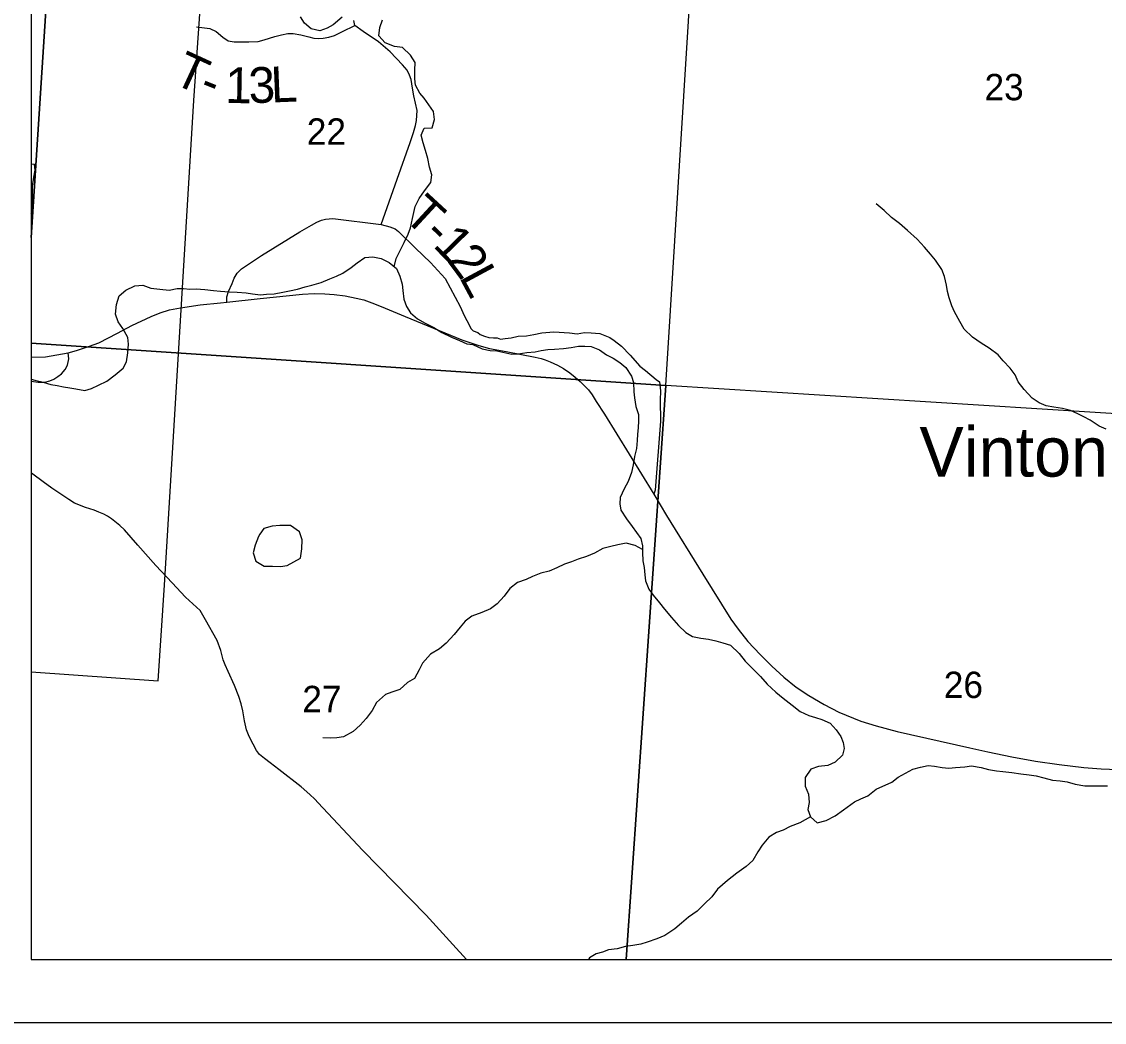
# Model space of a CAD drawing. Extents: x 0 to 34, y 0 to 22.
# Drawn here: x 2.085 to 3.804, y 14 to 15.589 of the extents above; entities that cross this region are included whole.
import ezdxf

# ---------------------------------------------------------------- set-up
doc = ezdxf.new("R2010")
doc.units = 0
for name, color, linetype in [('Default', 7, 'Continuous'), ('GM_X_City_Street', 7, 'Continuous'), ('GM_X_Minor_Lake', 7, 'Continuous'), ('GM_X_Minor_River', 7, 'Continuous'), ('GM_X_Section', 7, 'Continuous'), ('GM_X_Section_Text', 7, 'Continuous'), ('GM_X_Township_Road', 7, 'Continuous'), ('GM_X_Township_Road_Text', 7, 'Continuous'), ('GM_X_Unincorporated_Text', 7, 'Continuous'), ('GM_X_US_Route', 7, 'Continuous'), ('SC_Scratch1', 7, 'Continuous'), ('SH_Data', 7, 'Continuous')]:
    doc.layers.add(name, color=color, linetype=linetype)

msp = doc.modelspace()

# ---------------------------------------------------------------- linework, layer by layer
at = {"layer": 'Default'}
for points in [[(2.1, 16.1183), (2.1, 15.2462), (2.1564, 16.1145)], [(2.1, 15.2462), (2.1, 15.0784), (3.1079, 15.0113), (3.1721, 16.0496), (2.1564, 16.1145)], [(2.1, 15.8568), (2.1, 14.5567), (2.3019, 14.5422), (2.3116, 14.694), (2.3586, 15.464), (2.3842, 15.838)], [(2.1, 15.0784), (2.1, 14.1), (3.0447, 14.1), (3.1079, 15.0113)], [(3.0447, 14.1), (4.0548, 14.1), (4.1172, 14.9476), (3.1079, 15.0113)]]:
    msp.add_lwpolyline(points, close=True, dxfattribs=at)
at = {"layer": 'GM_X_City_Street'}
msp.add_line((2.1, 15.3633), (2.1057, 15.3627), dxfattribs=at)
for points in [[(2.1028, 15.2885), (2.1022, 15.309), (2.1024, 15.3276), (2.1044, 15.3421), (2.1065, 15.3531), (2.1057, 15.3627)], [(2.1, 15.2836), (2.1004, 15.2839), (2.1028, 15.2885)], [(2.1, 15.0179), (2.1113, 15.0164), (2.1218, 15.0166), (2.1299, 15.0188), (2.1364, 15.0215), (2.1427, 15.0254), (2.1484, 15.0297), (2.1541, 15.0367), (2.1578, 15.0437), (2.1599, 15.0535), (2.1589, 15.0629)], [(2.3239, 14.6977), (2.2979, 14.7256), (2.2694, 14.7579), (2.2483, 14.7819), (2.241, 14.789), (2.2332, 14.7952), (2.2275, 14.7995), (2.2214, 14.8036), (2.2155, 14.8069), (2.2077, 14.81), (2.2003, 14.8132), (2.1863, 14.8176), (2.1691, 14.8242), (2.1602, 14.8302), (2.1331, 14.8484), (2.119, 14.8582), (2.103, 14.8704), (2.1, 14.8728)]]:
    msp.add_lwpolyline(points, dxfattribs=at)
at = {"layer": 'GM_X_Minor_Lake'}
for points in [[(2.5278, 14.7369), (2.5297, 14.7517), (2.5305, 14.7661), (2.526, 14.779), (2.5116, 14.7889), (2.495, 14.7889), (2.4825, 14.7878), (2.4693, 14.7844), (2.4633, 14.7752)], [(2.4633, 14.7752), (2.4609, 14.7715), (2.456, 14.7579), (2.4526, 14.7458), (2.4567, 14.7325), (2.4703, 14.7245), (2.4832, 14.7245), (2.496, 14.7237), (2.5066, 14.7256), (2.5278, 14.7369)]]:
    msp.add_lwpolyline(points, dxfattribs=at)
at = {"layer": 'GM_X_Minor_River'}
for points in [[(2.5937, 15.5961), (2.5797, 15.5839), (2.5699, 15.5786), (2.5586, 15.5744), (2.5449, 15.5774), (2.5339, 15.5868), (2.5278, 15.5967)], [(2.7239, 15.4674), (2.7171, 15.4754), (2.7103, 15.4879), (2.7091, 15.4981), (2.709, 15.5118), (2.7098, 15.5243), (2.7025, 15.536), (2.6896, 15.5478), (2.6767, 15.5496), (2.662, 15.5553), (2.6521, 15.5666), (2.6536, 15.5795), (2.6581, 15.592)], [(2.6766, 15.1998), (2.6795, 15.2127), (2.6924, 15.2384), (2.6988, 15.2517), (2.7023, 15.2615), (2.7057, 15.2763), (2.7095, 15.2953), (2.7163, 15.3081), (2.7247, 15.3202), (2.7345, 15.3335), (2.7361, 15.346), (2.7327, 15.3581), (2.7297, 15.3718), (2.7263, 15.3843), (2.7222, 15.3964), (2.7195, 15.4089), (2.7241, 15.4199), (2.7366, 15.4203), (2.7404, 15.4335), (2.7389, 15.4464), (2.7239, 15.4674)], [(3.8065, 14.9419), (3.7955, 14.9469), (3.7815, 14.956), (3.7713, 14.9613), (3.7615, 14.9663), (3.7502, 14.9716), (3.7373, 14.9746), (3.7237, 14.9769), (3.7116, 14.9792), (3.7003, 14.9838), (3.6893, 14.991), (3.6765, 15.0047), (3.667, 15.0172), (3.6621, 15.0282), (3.6542, 15.0388), (3.6433, 15.0502), (3.635, 15.0597), (3.621, 15.0703), (3.6081, 15.0787), (3.5945, 15.0878), (3.5813, 15.1007), (3.5745, 15.1128), (3.5659, 15.128), (3.5617, 15.1378), (3.5572, 15.1504), (3.5549, 15.1606), (3.5531, 15.1708), (3.5501, 15.1841), (3.5459, 15.1955), (3.5357, 15.2103), (3.5278, 15.2198), (3.5184, 15.2308), (3.5067, 15.2437), (3.4912, 15.2573), (3.4787, 15.2687), (3.4659, 15.2782), (3.4542, 15.2892), (3.4413, 15.2995)], [(2.5353, 15.1678), (2.5459, 15.1704), (2.5603, 15.1746), (2.5743, 15.1806), (2.5849, 15.1848), (2.5951, 15.1897), (2.608, 15.1988), (2.6178, 15.206), (2.63, 15.2143), (2.6428, 15.2154), (2.6557, 15.2127), (2.6685, 15.2066), (2.6802, 15.1968), (2.6855, 15.185), (2.6889, 15.1721), (2.69, 15.1619), (2.6919, 15.1486), (2.696, 15.1365), (2.7024, 15.1266), (2.7134, 15.1171), (2.7258, 15.1103), (2.7394, 15.1031), (2.7523, 15.0955), (2.7674, 15.0879), (2.7803, 15.0825), (2.7916, 15.0776), (2.8014, 15.0761), (2.8162, 15.0696), (2.8286, 15.0669), (2.8396, 15.0662), (2.8536, 15.0631), (2.8634, 15.0612), (2.8733, 15.0616), (2.8869, 15.0638), (2.9001, 15.0649), (2.91, 15.0668), (2.9205, 15.0683), (2.9308, 15.0691), (2.9451, 15.0702), (2.9576, 15.0717), (2.969, 15.0735), (2.9792, 15.0739), (2.989, 15.0731), (3.0026, 15.0678), (3.0136, 15.0602), (3.0242, 15.0545), (3.0344, 15.0477), (3.0442, 15.0397), (3.0532, 15.0261), (3.0562, 15.0162), (3.0566, 15.0014), (3.0577, 14.9919), (3.0603, 14.9779), (3.0645, 14.9654), (3.0645, 14.9552), (3.0637, 14.9438), (3.0625, 14.9339), (3.0621, 14.9237), (3.061, 14.9112), (3.0579, 14.8983), (3.0556, 14.8855), (3.0534, 14.8729), (3.0477, 14.8589), (3.0416, 14.8472), (3.0351, 14.8336), (3.0344, 14.8233), (3.0362, 14.8135), (3.0453, 14.7998), (3.0543, 14.7873), (3.0679, 14.7683), (3.0706, 14.7566), (3.0705, 14.7463), (3.0713, 14.7331), (3.0732, 14.7225), (3.0743, 14.7107), (3.0754, 14.7009), (3.0807, 14.688), (3.0875, 14.6781), (3.0976, 14.666), (3.1056, 14.6561), (3.1169, 14.6428), (3.1278, 14.6303), (3.1395, 14.6189), (3.1501, 14.6125), (3.163, 14.6098), (3.1755, 14.6082), (3.1868, 14.606), (3.1981, 14.6025), (3.2102, 14.5987), (3.2242, 14.5858), (3.2336, 14.5737), (3.2461, 14.5608), (3.2578, 14.549), (3.2684, 14.5369), (3.2823, 14.5243), (3.2941, 14.5148), (3.308, 14.5038), (3.3209, 14.4936), (3.3345, 14.4875), (3.3451, 14.4841), (3.3553, 14.4807)], [(2.1, 15.0211), (2.1058, 15.0199), (2.1194, 15.0165), (2.1312, 15.013), (2.1414, 15.0115), (2.1516, 15.0092), (2.1614, 15.0073), (2.1712, 15.0058), (2.1856, 15.0035), (2.1962, 15.0065), (2.2072, 15.0118), (2.2204, 15.0182), (2.2337, 15.028), (2.2462, 15.039), (2.2515, 15.0489), (2.2538, 15.0633), (2.2549, 15.0769), (2.2538, 15.0875), (2.2455, 15.1019), (2.2384, 15.1122), (2.2338, 15.1247), (2.2358, 15.1398), (2.2399, 15.1538), (2.2505, 15.1625), (2.2645, 15.1693), (2.2774, 15.1705), (2.2899, 15.1659), (2.3042, 15.1644), (2.319, 15.1628), (2.3322, 15.1651), (2.3421, 15.1654), (2.3519, 15.1643), (2.3621, 15.1647), (2.3757, 15.1639), (2.3897, 15.162), (2.4007, 15.1612), (2.4147, 15.16), (2.4271, 15.1592), (2.4415, 15.1585), (2.4517, 15.1569), (2.4642, 15.1554), (2.474, 15.1561), (2.4861, 15.1569), (2.4998, 15.1595), (2.5104, 15.1614), (2.5232, 15.1644), (2.5353, 15.1678)], [(3.0705, 14.7509), (3.0588, 14.7574), (3.0449, 14.7608), (3.0312, 14.7585), (3.0206, 14.7555), (3.0078, 14.7525), (2.9945, 14.7449), (2.9817, 14.7397), (2.9684, 14.7355), (2.9578, 14.7314), (2.9468, 14.7276), (2.9344, 14.7215), (2.9226, 14.7166), (2.9094, 14.7132), (2.8958, 14.708), (2.8859, 14.7034), (2.8723, 14.6985), (2.8602, 14.6891), (2.8511, 14.6766), (2.8397, 14.6645), (2.8295, 14.6565), (2.8155, 14.6509), (2.7996, 14.6448), (2.789, 14.6372), (2.781, 14.6274), (2.7719, 14.6157), (2.759, 14.602), (2.7484, 14.5933), (2.7341, 14.5847), (2.7212, 14.5703), (2.7159, 14.56), (2.7087, 14.546), (2.6977, 14.5396), (2.6856, 14.5286), (2.6727, 14.5241), (2.6629, 14.5207), (2.6485, 14.5079), (2.6413, 14.4954), (2.6322, 14.4825), (2.6223, 14.4719), (2.6113, 14.4617), (2.5958, 14.4534), (2.5856, 14.4519), (2.5758, 14.4511), (2.5633, 14.4519)], [(3.3553, 14.4807), (3.3685, 14.4753), (3.3779, 14.4643), (3.3855, 14.4537), (3.3892, 14.4442), (3.3907, 14.4347), (3.3881, 14.4245), (3.3767, 14.4132), (3.365, 14.4079), (3.3502, 14.4064), (3.3377, 14.4022), (3.329, 14.3886), (3.329, 14.375), (3.3343, 14.3624), (3.335, 14.3492), (3.3331, 14.3382), (3.3372, 14.3261), (3.3478, 14.3166), (3.3622, 14.3203), (3.3762, 14.3279), (3.3898, 14.3377), (3.4069, 14.3502), (3.4171, 14.3547), (3.4284, 14.3597), (3.4413, 14.3702), (3.4663, 14.3816), (3.4765, 14.3891), (3.4879, 14.3959), (3.4996, 14.402), (3.5117, 14.4054), (3.5242, 14.4076), (3.534, 14.4069), (3.5465, 14.4046), (3.5571, 14.4038), (3.5673, 14.4049), (3.5824, 14.406), (3.593, 14.4075), (3.6082, 14.4049), (3.6199, 14.4014), (3.6327, 14.3995), (3.6426, 14.3984), (3.6569, 14.3965), (3.6713, 14.3945), (3.6845, 14.393), (3.6955, 14.3915), (3.7076, 14.3884), (3.7216, 14.3846), (3.7337, 14.3835), (3.745, 14.3819), (3.7575, 14.3781), (3.7726, 14.3754), (3.8089, 14.3754)], [(3.3372, 14.3261), (3.3202, 14.3166), (3.3051, 14.3109), (3.2937, 14.3053), (3.2835, 14.3015), (3.2714, 14.2939), (3.2608, 14.2811), (3.2539, 14.2709), (3.2456, 14.2568), (3.2354, 14.2474), (3.2202, 14.2368), (3.2058, 14.2251), (3.1899, 14.2115), (3.1808, 14.1993), (3.1691, 14.1884), (3.1573, 14.1763), (3.1437, 14.1668), (3.1324, 14.1573), (3.1221, 14.1486), (3.1062, 14.1377), (3.0934, 14.1324), (3.0782, 14.1275), (3.068, 14.1241), (3.0551, 14.1222), (3.0434, 14.1203), (3.0302, 14.1166), (3.0169, 14.1151), (3.0071, 14.1117), (2.9969, 14.109), (2.9863, 14.1022), (2.9851, 14.1)]]:
    msp.add_lwpolyline(points, dxfattribs=at)
at = {"layer": 'GM_X_Section'}
msp.add_lwpolyline([(4.189, 15.9719), (4.1172, 14.9476), (3.1079, 15.0113), (3.1721, 16.0496)], close=True, dxfattribs=at)
at = {"layer": 'GM_X_Township_Road'}
for points in [[(2.656, 15.267), (2.681, 15.339), (2.7019, 15.3972), (2.7073, 15.4128), (2.7103, 15.4243), (2.7117, 15.4323), (2.7126, 15.4402), (2.7128, 15.448), (2.7101, 15.4597), (2.7075, 15.4714), (2.7053, 15.4833), (2.7033, 15.4969), (2.7006, 15.5043), (2.6971, 15.5119), (2.6894, 15.5207), (2.6701, 15.5411), (2.6515, 15.5572), (2.6273, 15.5735), (2.614, 15.5828), (2.6126, 15.5908)], [(2.3627, 15.5806), (2.3839, 15.5781), (2.3937, 15.5733), (2.4043, 15.5645), (2.4131, 15.5587), (2.4226, 15.5568), (2.4459, 15.557), (2.4605, 15.5577), (2.4701, 15.56), (2.4868, 15.5652), (2.4978, 15.5683), (2.5078, 15.5704), (2.5163, 15.5702), (2.528, 15.5681), (2.5407, 15.5647), (2.549, 15.5629), (2.5567, 15.5622), (2.5638, 15.5629), (2.5725, 15.5645), (2.5819, 15.5672), (2.5944, 15.5735), (2.614, 15.5828)], [(2.4108, 15.1438), (2.4108, 15.1518), (2.4133, 15.1604), (2.4195, 15.173), (2.4223, 15.1817), (2.4274, 15.1898), (2.4338, 15.1967), (2.4659, 15.2179), (2.5269, 15.2555), (2.5454, 15.2659), (2.5539, 15.2707), (2.5611, 15.274), (2.5674, 15.2754), (2.579, 15.2763), (2.656, 15.267)], [(2.656, 15.267), (2.6697, 15.2633), (2.6779, 15.26), (2.6832, 15.256), (2.7105, 15.2294), (2.7341, 15.2066), (2.7574, 15.1813), (2.781, 15.1365), (2.7874, 15.1222), (2.796, 15.1065), (2.7982, 15.1017), (2.802, 15.0979), (2.809, 15.0953), (2.813, 15.0925), (2.82, 15.0898), (2.8267, 15.0874), (2.834, 15.0869), (2.8399, 15.0869), (2.8452, 15.0849), (2.8525, 15.0858), (2.8622, 15.0872), (2.8734, 15.0894), (2.8864, 15.0903), (2.8979, 15.0922), (2.9109, 15.0947), (2.9301, 15.0964), (2.9548, 15.0949), (2.9671, 15.0933), (2.9784, 15.0953), (2.9892, 15.0951), (3.0028, 15.0938), (3.0185, 15.0874), (3.0257, 15.0828), (3.0372, 15.0739), (3.0509, 15.0592), (3.0665, 15.0418), (3.0753, 15.0351), (3.0925, 15.021), (3.0978, 15.0173), (3.099, 15.0027), (3.0989, 14.988), (3.0992, 14.9544), (3.0906, 14.8451), (3.0886, 14.8389)], [(2.7911, 14.1), (2.7697, 14.1236), (2.727, 14.1703), (2.6263, 14.2734), (2.5556, 14.3484), (2.5506, 14.3545), (2.5424, 14.362), (2.5288, 14.3739), (2.4931, 14.4016), (2.4796, 14.4123), (2.4708, 14.4191), (2.4626, 14.4252), (2.458, 14.4319), (2.4525, 14.4418), (2.4462, 14.454), (2.4419, 14.4646), (2.4388, 14.479), (2.4362, 14.4945), (2.4334, 14.5058), (2.4296, 14.5174), (2.4227, 14.5351), (2.4129, 14.5569), (2.4083, 14.5675), (2.4048, 14.5756), (2.4011, 14.5904), (2.3952, 14.6066), (2.3769, 14.6393), (2.3684, 14.6541), (2.3453, 14.6752), (2.3239, 14.6977)]]:
    msp.add_lwpolyline(points, dxfattribs=at)
at = {"layer": 'GM_X_US_Route'}
for points in [[(2.1, 15.0566), (2.1013, 15.0564), (2.1231, 15.0569), (2.1589, 15.0629), (2.1724, 15.0671), (2.1927, 15.0737), (2.2075, 15.0791), (2.2371, 15.0945), (2.2601, 15.1067), (2.2906, 15.1209), (2.305, 15.1266), (2.32, 15.1312), (2.3373, 15.1346), (2.3686, 15.1392), (2.4005, 15.1426)], [(2.4005, 15.1426), (2.4108, 15.1438), (2.4636, 15.1493), (2.531, 15.1564), (2.5495, 15.1573), (2.5661, 15.157), (2.5811, 15.1557), (2.5987, 15.1535), (2.6163, 15.1502), (2.6282, 15.1471), (2.641, 15.1427), (2.6558, 15.1368), (2.694, 15.1209), (2.7839, 15.0838), (2.8108, 15.075), (2.8278, 15.07), (2.8542, 15.0655), (2.9001, 15.0565), (2.9096, 15.0539), (2.9162, 15.0519), (2.9239, 15.049), (2.9356, 15.0435), (2.945, 15.0382), (2.9552, 15.0316), (2.9638, 15.0246), (2.9719, 15.0177), (2.9779, 15.0115), (2.9847, 15.0045), (2.9905, 14.9963), (2.9969, 14.9858), (3.0101, 14.9659), (3.0886, 14.8389), (3.1087, 14.805), (3.1662, 14.7115), (3.211, 14.6401), (3.2224, 14.6242), (3.2376, 14.605), (3.2575, 14.5841), (3.2757, 14.5658), (3.2949, 14.5483), (3.3148, 14.5324), (3.3346, 14.519), (3.3591, 14.5049), (3.3825, 14.4928), (3.4171, 14.4785), (3.4418, 14.4707), (3.4751, 14.4619), (3.5901, 14.4357), (3.619, 14.4296)], [(3.619, 14.4296), (3.6567, 14.4216), (3.6946, 14.4147), (3.7323, 14.4092), (3.7712, 14.4046), (3.7989, 14.4026), (3.839, 14.4009), (3.8649, 14.4004), (3.8957, 14.4004), (3.943, 14.4026), (3.9957, 14.405)]]:
    msp.add_lwpolyline(points, dxfattribs=at)
at = {"layer": 'SC_Scratch1'}
msp.add_lwpolyline([(2.1, 19.1982), (2.1, 14.1), (5.0535, 14.1), (5.0814, 14.5016), (5.1049, 14.8414), (5.1794, 15.9156), (5.2761, 17.2534), (5.2869, 17.4026), (5.3506, 18.2846), (5.3662, 18.4999), (5.4007, 18.9779), (5.182, 18.9932), (4.7997, 19.0196), (4.7394, 19.0241), (4.3628, 19.0495), (3.3448, 19.1146), (2.3572, 19.1804)], close=True, dxfattribs=at)
at = {"layer": 'SH_Data'}
for p, q in [((2.1, 20.9), (2.1, 14.1)), ((2.1, 14.1), (8.9, 14.1)), ((2.1, 14.1), (2.1, 14.1)), ((2, 14), (9, 14))]:
    msp.add_line(p, q, dxfattribs=at)

# ---------------------------------------------------------------- texts
at = {"layer": 'GM_X_Section_Text'}
for s, p in [('23', (3.6135, 15.4642)), ('22', (2.5377, 15.3936)), ('26', (3.5489, 14.515)), ('27', (2.5306, 14.4925))]:
    msp.add_text(s, height=0.04186, rotation=0, dxfattribs=at).set_placement(p)
at = {"layer": 'GM_X_Township_Road_Text'}
for s, rotation, p in [('T', 335.2329, (2.3228, 15.4922)), ('1', 359.0172, (2.4079, 15.46)), ('3', 1.9289, (2.4461, 15.4594)), ('L', 2.3166, (2.4815, 15.4606)), ('-', 338.1589, (2.3643, 15.4731)), ('T', 317.2609, (2.6893, 15.2774)), ('-', 315.6171, (2.7202, 15.2489)), ('1', 314.3369, (2.7365, 15.233)), ('2', 306.5952, (2.7594, 15.2097)), ('L', 298.3385, (2.7789, 15.1836))]:
    msp.add_text(s, height=0.0568, rotation=rotation, dxfattribs=at).set_placement(p)
at = {"layer": 'GM_X_Unincorporated_Text'}
msp.add_text('Vinton', height=0.07898, rotation=0, dxfattribs=at).set_placement((3.5102, 14.8666))

doc.saveas('drawing.dxf')
